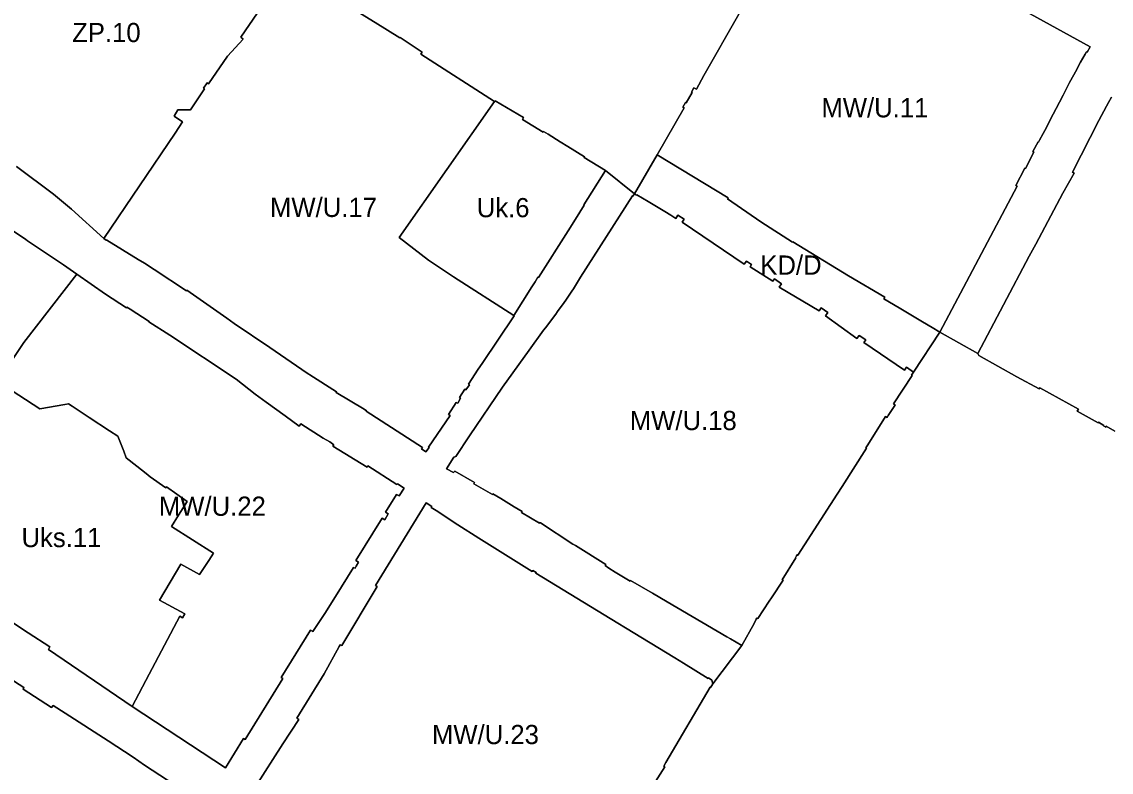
# Model space of a CAD drawing. Extents: x 7423367 to 7424726, y 5546744 to 5548391.
# Drawn here: x 7423643.2 to 7423927, y 5547840.8 to 5548036.2 of the extents above; entities that cross this region are included whole.
import ezdxf

# ---------------------------------------------------------------- set-up
doc = ezdxf.new("R2010")
doc.units = 0
doc.layers.add('linie_rozgraniczajace', color=7, linetype='Continuous')
doc.layers.add('oznaczenia_przeznaczen', color=7, linetype='Continuous')

msp = doc.modelspace()

# ---------------------------------------------------------------- linework, layer by layer
at = {"layer": 'linie_rozgraniczajace'}
for points in [[(7423885.09, 5548049.88), (7423921.52, 5548029.77), (7423920.73, 5548028.36), (7423920.59, 5548028.44), (7423920.26, 5548027.84), (7423919.06, 5548025.7), (7423917.72, 5548023.24), (7423916.54, 5548021.09), (7423916.19, 5548020.45), (7423914.8, 5548017.67), (7423914.53, 5548017.11), (7423913.56, 5548015.33), (7423911.05, 5548010.55), (7423910.14, 5548008.72), (7423909.29, 5548007.19), (7423908.36, 5548005.42), (7423908.1, 5548004.94), (7423908.01, 5548004.98), (7423906.64, 5548002.5), (7423906.89, 5548002.31), (7423904.69, 5547998.03), (7423904.56, 5547998.1), (7423902.22, 5547993.58), (7423902.52, 5547993.43), (7423882.35, 5547955.46), (7423880.38, 5547956.62), (7423877.9, 5547958.07), (7423872.18, 5547961.46), (7423870.28, 5547962.6), (7423867.78, 5547964.11), (7423868.05, 5547964.53), (7423858.62, 5547970.07), (7423844.04, 5547978.98), (7423843.97, 5547978.87), (7423835.77, 5547984.17), (7423827.04, 5547990.13), (7423827.22, 5547990.39), (7423808.74, 5548001.62), (7423815.79, 5548013.83), (7423815.44, 5548014.04), (7423816.14, 5548015.19), (7423816.27, 5548015.11), (7423817.81, 5548017.81), (7423817.67, 5548017.89), (7423818.27, 5548019.04), (7423818.96, 5548018.68), (7423820.91, 5548022.25), (7423830.03, 5548038.21)], [(7423927.11, 5548016.65), (7423926.3, 5548015.23), (7423925.83, 5548014.29), (7423923.84, 5548010.57), (7423916.91, 5547997.09), (7423917.36, 5547996.85), (7423914.45, 5547991.58), (7423907.39, 5547978.36), (7423905.67, 5547975.22), (7423892.25, 5547949.89), (7423882.35, 5547955.46), (7423902.52, 5547993.43), (7423902.22, 5547993.58), (7423904.56, 5547998.1), (7423904.69, 5547998.03), (7423906.89, 5548002.31), (7423906.64, 5548002.5), (7423908.01, 5548004.98), (7423908.1, 5548004.94), (7423908.36, 5548005.42), (7423909.29, 5548007.19), (7423910.14, 5548008.72), (7423911.05, 5548010.55), (7423913.56, 5548015.33), (7423914.53, 5548017.11), (7423914.8, 5548017.67), (7423916.19, 5548020.45), (7423916.54, 5548021.09), (7423917.72, 5548023.24), (7423919.06, 5548025.7), (7423920.26, 5548027.84), (7423920.59, 5548028.44), (7423920.73, 5548028.36), (7423921.52, 5548029.77), (7423885.09, 5548049.88)], [(7423710.1, 5548046.67), (7423700.22, 5548032.28), (7423700.88, 5548031.75), (7423696.81, 5548027.33), (7423691.85, 5548020.1), (7423691.5, 5548020.34), (7423690.54, 5548018.95), (7423690.83, 5548018.75), (7423687.17, 5548013.29), (7423683.85, 5548013.29), (7423682.85, 5548011.68), (7423685.07, 5548010.16), (7423683.14, 5548007.28), (7423664.55, 5547979.8), (7423656.16, 5547987.48), (7423651.46, 5547991.4), (7423641.85, 5547998.56)], [(7423725.35, 5548042.21), (7423735.28, 5548036.08), (7423741.7, 5548032.06), (7423741.77, 5548032.13), (7423747.51, 5548028.35), (7423747.14, 5548027.86), (7423766.34, 5548015.45), (7423741.48, 5547980.05), (7423749.19, 5547974.17), (7423755.66, 5547969.79), (7423771.37, 5547959.73), (7423771.51, 5547959.64), (7423763.12, 5547947.28), (7423762.11, 5547945.8), (7423759.6, 5547941.86), (7423759.84, 5547941.68), (7423758.89, 5547940.43), (7423758.64, 5547940.57), (7423757.19, 5547938.41), (7423757.52, 5547938.21), (7423756.79, 5547936.94), (7423756.34, 5547937.08), (7423754.37, 5547933.96), (7423754.78, 5547933.68), (7423749.15, 5547925.51), (7423749.3, 5547925.41), (7423748.49, 5547924.24), (7423747.31, 5547925.01), (7423747.55, 5547925.37), (7423732.92, 5547934.82), (7423733, 5547934.95), (7423732.36, 5547935.34), (7423725.08, 5547939.75), (7423725.15, 5547939.86), (7423718.24, 5547944.32), (7423717.98, 5547944.48), (7423717.52, 5547944.76), (7423707.84, 5547951.4), (7423698.55, 5547957.67), (7423696.59, 5547959.07), (7423686.22, 5547966.37), (7423686.11, 5547966.22), (7423677.64, 5547971.78), (7423675.13, 5547973.35), (7423673.55, 5547974.36), (7423665.31, 5547979.42), (7423665.19, 5547979.37), (7423664.55, 5547979.8), (7423683.14, 5548007.28), (7423685.07, 5548010.16), (7423682.85, 5548011.68), (7423683.85, 5548013.29), (7423687.17, 5548013.29), (7423690.83, 5548018.75), (7423690.54, 5548018.95), (7423691.5, 5548020.34), (7423691.85, 5548020.1), (7423696.81, 5548027.33), (7423700.88, 5548031.75), (7423700.22, 5548032.28), (7423710.1, 5548046.67)], [(7423830.03, 5548038.21), (7423820.91, 5548022.25), (7423818.96, 5548018.68), (7423818.27, 5548019.04), (7423817.67, 5548017.89), (7423817.81, 5548017.81), (7423816.27, 5548015.11), (7423816.14, 5548015.19), (7423815.44, 5548014.04), (7423815.79, 5548013.83), (7423808.74, 5548001.62), (7423802.79, 5547991.41), (7423795.28, 5547997.5), (7423789.69, 5548000.9), (7423789.79, 5548001.07), (7423785.47, 5548003.77), (7423783.44, 5548005.02), (7423780.3, 5548006.95), (7423779.1, 5548007.67), (7423779.01, 5548007.51), (7423773.64, 5548010.84), (7423773.87, 5548011.29), (7423766.49, 5548015.69), (7423766.34, 5548015.45), (7423747.14, 5548027.86), (7423747.51, 5548028.35), (7423741.77, 5548032.13), (7423741.7, 5548032.06), (7423735.28, 5548036.08), (7423725.35, 5548042.21)], [(7423927.97, 5547929.6), (7423925.73, 5547930.91), (7423925.61, 5547930.67), (7423924.99, 5547930.99), (7423925.07, 5547931.14), (7423923.71, 5547931.94), (7423923.61, 5547931.77), (7423918.19, 5547934.83), (7423918.54, 5547935.37), (7423908.44, 5547940.95), (7423908.29, 5547940.68), (7423902.4, 5547943.78), (7423892.52, 5547949.37), (7423892.25, 5547949.89), (7423905.67, 5547975.22), (7423907.39, 5547978.36), (7423914.45, 5547991.58), (7423917.36, 5547996.85), (7423916.91, 5547997.09), (7423923.84, 5548010.57), (7423925.83, 5548014.29), (7423926.3, 5548015.23), (7423927.11, 5548016.65)], [(7423641.85, 5547998.56), (7423651.46, 5547991.4), (7423656.16, 5547987.48), (7423664.55, 5547979.8), (7423665.19, 5547979.37), (7423665.31, 5547979.42), (7423673.55, 5547974.36), (7423675.13, 5547973.35), (7423677.64, 5547971.78), (7423686.11, 5547966.22), (7423686.22, 5547966.37), (7423696.59, 5547959.07), (7423698.55, 5547957.67), (7423707.84, 5547951.4), (7423717.52, 5547944.76), (7423717.98, 5547944.48), (7423718.24, 5547944.32), (7423725.15, 5547939.86), (7423725.08, 5547939.75), (7423732.36, 5547935.34), (7423733, 5547934.95), (7423732.92, 5547934.82), (7423747.55, 5547925.37), (7423747.31, 5547925.01), (7423748.49, 5547924.24), (7423749.3, 5547925.41), (7423749.15, 5547925.51), (7423754.78, 5547933.68), (7423754.37, 5547933.96), (7423756.34, 5547937.08), (7423756.79, 5547936.94), (7423757.52, 5547938.21), (7423757.19, 5547938.41), (7423758.64, 5547940.57), (7423758.89, 5547940.43), (7423759.84, 5547941.68), (7423759.6, 5547941.86), (7423762.11, 5547945.8), (7423763.12, 5547947.28), (7423771.51, 5547959.64), (7423771.37, 5547959.73), (7423776.07, 5547967.19), (7423776.93, 5547968.57), (7423777.67, 5547969.74), (7423777.81, 5547969.65), (7423785.56, 5547981.81), (7423787.49, 5547984.84), (7423789.75, 5547988.46), (7423789.6, 5547988.55), (7423795.28, 5547997.5), (7423802.79, 5547991.41), (7423802.43, 5547990.81), (7423802.3, 5547990.92), (7423788.74, 5547969.75), (7423788.8, 5547969.71), (7423786.9, 5547966.72), (7423786.47, 5547966.08), (7423784.94, 5547963.75), (7423784.5, 5547963.13), (7423782.78, 5547960.76), (7423782.3, 5547960.11), (7423779.61, 5547956.53), (7423779.16, 5547955.91), (7423775.37, 5547950.77), (7423768.42, 5547941.11), (7423759.88, 5547928.43), (7423756.26, 5547923.03), (7423755.74, 5547922.87), (7423753.88, 5547919.84), (7423755.63, 5547918.85), (7423756.05, 5547919.24), (7423761.16, 5547916.31), (7423760.94, 5547915.93), (7423765.79, 5547913.12), (7423765.92, 5547913.33), (7423767.98, 5547912.06), (7423771.49, 5547909.94), (7423773.52, 5547908.72), (7423773.38, 5547908.48), (7423778.05, 5547905.65), (7423778.18, 5547905.87), (7423778.3, 5547905.79), (7423786.8, 5547900.23), (7423787.47, 5547899.82), (7423795.34, 5547894.88), (7423795.18, 5547894.64), (7423796.14, 5547893.99), (7423797.81, 5547892.96), (7423801.71, 5547890.56), (7423801.81, 5547890.73), (7423807.55, 5547887.48), (7423811.38, 5547885.21), (7423826.89, 5547876.06), (7423827.82, 5547875.57), (7423830.78, 5547873.78), (7423823.24, 5547863.84), (7423822.97, 5547864.82), (7423822.08, 5547865.39), (7423822.01, 5547865.27), (7423815.61, 5547869.21), (7423813.35, 5547870.61), (7423800.51, 5547878.46), (7423798.51, 5547879.65), (7423777.08, 5547892.63), (7423777.19, 5547892.82), (7423776.34, 5547893.37), (7423776.18, 5547893.06), (7423762.27, 5547901.73), (7423756.79, 5547905.21), (7423751.12, 5547908.95), (7423749.88, 5547909.77), (7423750.04, 5547910.02), (7423748.55, 5547910.97), (7423735.38, 5547889.46), (7423735.79, 5547889.21), (7423726.57, 5547873.83), (7423726.18, 5547874.03), (7423725.9, 5547873.53), (7423722, 5547866.46), (7423714.83, 5547854.87), (7423715.35, 5547854.54), (7423711.24, 5547848.23), (7423703.96, 5547836.97)], [(7423630.41, 5547988.72), (7423644.27, 5547979.52), (7423644.67, 5547979.21), (7423654.03, 5547972.95), (7423657.55, 5547970.55), (7423643.76, 5547952.76), (7423636.86, 5547942.57)], [(7423640.25, 5547880.13), (7423644.87, 5547877.13), (7423650.51, 5547873.45), (7423650.14, 5547872.82), (7423671.93, 5547857.91), (7423696.24, 5547841.95), (7423700.96, 5547849.62), (7423701.41, 5547849.32), (7423711.16, 5547865.26), (7423710.73, 5547865.53), (7423718.45, 5547877.85), (7423719, 5547877.48), (7423722.13, 5547882.17), (7423724.89, 5547886.57), (7423729.64, 5547894.17), (7423730.03, 5547893.96), (7423730.35, 5547894.51), (7423730.94, 5547895.51), (7423730.22, 5547895.96), (7423737.11, 5547907.02), (7423737.79, 5547906.58), (7423738.69, 5547908.13), (7423737.97, 5547908.55), (7423740.86, 5547913.16), (7423741.48, 5547912.77), (7423742.78, 5547914.81), (7423741.04, 5547915.94), (7423740.94, 5547915.78), (7423733.36, 5547920.65), (7423733.14, 5547920.26), (7423724.27, 5547925.69), (7423724.5, 5547926.1), (7423724.11, 5547926.36), (7423723.42, 5547926.83), (7423721.68, 5547927.85), (7423715.93, 5547931.57), (7423715.49, 5547930.91), (7423711.79, 5547933.62), (7423706.86, 5547937.2), (7423703.96, 5547939.29), (7423699.06, 5547943.2), (7423681.8, 5547954.6), (7423676.33, 5547958.09), (7423676.41, 5547958.22), (7423671.42, 5547961.38), (7423670.57, 5547961.92), (7423670.51, 5547961.8), (7423664.98, 5547965.28), (7423657.55, 5547970.55), (7423654.03, 5547972.95), (7423644.67, 5547979.21), (7423644.27, 5547979.52), (7423630.41, 5547988.72)], [(7423807.72, 5547837.46), (7423810.74, 5547842.25), (7423810.48, 5547842.41), (7423811.01, 5547843.31), (7423822.57, 5547863), (7423822.68, 5547862.93), (7423823.24, 5547863.84), (7423830.78, 5547873.78), (7423833.97, 5547879.57), (7423834.55, 5547880.7), (7423834.7, 5547880.95), (7423834.92, 5547880.82), (7423837.93, 5547885.35), (7423838.53, 5547886.25), (7423841.52, 5547890.8), (7423841.31, 5547890.94), (7423844.82, 5547896.62), (7423844.74, 5547896.68), (7423845.06, 5547897.15), (7423845.24, 5547897.41), (7423845.34, 5547897.34), (7423855.63, 5547913.2), (7423856.9, 5547915.19), (7423863.26, 5547925.17), (7423863.06, 5547925.31), (7423863.62, 5547926.11), (7423868.2, 5547933.46), (7423868.63, 5547933.19), (7423868.96, 5547933.68), (7423870.49, 5547936.03), (7423870.77, 5547936.49), (7423870.33, 5547936.75), (7423875.16, 5547944.17), (7423875.04, 5547944.25), (7423875.5, 5547945.01), (7423882.35, 5547955.46), (7423892.25, 5547949.89), (7423892.52, 5547949.37), (7423902.4, 5547943.78), (7423908.29, 5547940.68), (7423908.44, 5547940.95), (7423918.54, 5547935.37), (7423918.19, 5547934.83), (7423923.61, 5547931.77), (7423923.71, 5547931.94), (7423925.07, 5547931.14), (7423924.99, 5547930.99), (7423925.61, 5547930.67), (7423925.73, 5547930.91), (7423927.97, 5547929.6)], [(7423636.86, 5547942.57), (7423647.87, 5547935.43), (7423654.41, 5547936.55), (7423655.4, 5547936.74), (7423656.34, 5547936.12), (7423660.74, 5547933.23), (7423666.01, 5547929.73), (7423668.23, 5547928.36), (7423669.81, 5547924.41), (7423670.38, 5547922.73), (7423673.14, 5547920.55), (7423675.58, 5547918.59), (7423676.62, 5547917.76), (7423680.74, 5547914.89), (7423680.88, 5547915.1), (7423686.29, 5547911.35), (7423684.03, 5547907.72), (7423682.18, 5547904.78), (7423693.17, 5547897.85), (7423691.9, 5547895.95), (7423689.46, 5547892.29), (7423684.65, 5547894.97), (7423679.03, 5547885.65), (7423685.63, 5547882.07), (7423685.03, 5547881.04), (7423684.35, 5547881.43), (7423676.36, 5547866.35), (7423671.93, 5547857.91), (7423650.14, 5547872.82), (7423650.51, 5547873.45), (7423644.87, 5547877.13), (7423640.25, 5547880.13)], [(7423703.96, 5547836.97), (7423711.24, 5547848.23), (7423715.35, 5547854.54), (7423714.83, 5547854.87), (7423722, 5547866.46), (7423725.9, 5547873.53), (7423726.18, 5547874.03), (7423726.57, 5547873.83), (7423735.79, 5547889.21), (7423735.38, 5547889.46), (7423748.55, 5547910.97), (7423750.04, 5547910.02), (7423749.88, 5547909.77), (7423751.12, 5547908.95), (7423756.79, 5547905.21), (7423762.27, 5547901.73), (7423776.18, 5547893.06), (7423776.34, 5547893.37), (7423777.19, 5547892.82), (7423777.08, 5547892.63), (7423798.51, 5547879.65), (7423800.51, 5547878.46), (7423813.35, 5547870.61), (7423815.61, 5547869.21), (7423822.01, 5547865.27), (7423822.08, 5547865.39), (7423822.97, 5547864.82), (7423823.24, 5547863.84), (7423822.68, 5547862.93), (7423822.57, 5547863), (7423811.01, 5547843.31), (7423810.48, 5547842.41), (7423810.74, 5547842.25), (7423807.72, 5547837.46)], [(7423599.17, 5547838.24), (7423590.07, 5547843.46), (7423595.31, 5547852.66), (7423594.21, 5547853.26), (7423605.47, 5547872.61), (7423606.55, 5547871.98), (7423611.45, 5547880.43), (7423620.5, 5547875.26), (7423621.63, 5547877.07), (7423643.75, 5547862.87), (7423643.56, 5547862.47), (7423650.96, 5547857.64), (7423651.33, 5547858.21), (7423654.49, 5547856.17), (7423665.68, 5547848.96), (7423672.17, 5547844.7), (7423675.14, 5547842.66), (7423691.1, 5547832.28)], [(7423691.1, 5547832.28), (7423675.14, 5547842.66), (7423672.17, 5547844.7), (7423665.68, 5547848.96), (7423654.49, 5547856.17), (7423651.33, 5547858.21), (7423650.96, 5547857.64), (7423643.56, 5547862.47), (7423643.75, 5547862.87), (7423621.63, 5547877.07)]]:
    msp.add_lwpolyline(points, dxfattribs=at)
for points in [[(7423741.48, 5547980.05), (7423766.34, 5548015.45), (7423766.49, 5548015.69), (7423773.87, 5548011.29), (7423773.64, 5548010.84), (7423779.01, 5548007.51), (7423779.1, 5548007.67), (7423780.3, 5548006.95), (7423783.44, 5548005.02), (7423785.47, 5548003.77), (7423789.79, 5548001.07), (7423789.69, 5548000.9), (7423795.28, 5547997.5), (7423789.6, 5547988.55), (7423789.75, 5547988.46), (7423787.49, 5547984.84), (7423785.56, 5547981.81), (7423777.81, 5547969.65), (7423777.67, 5547969.74), (7423776.93, 5547968.57), (7423776.07, 5547967.19), (7423771.37, 5547959.73), (7423755.66, 5547969.79), (7423749.19, 5547974.17)], [(7423802.79, 5547991.41), (7423808.74, 5548001.62), (7423827.22, 5547990.39), (7423827.04, 5547990.13), (7423835.77, 5547984.17), (7423843.97, 5547978.87), (7423844.04, 5547978.98), (7423858.62, 5547970.07), (7423868.05, 5547964.53), (7423867.78, 5547964.11), (7423870.28, 5547962.6), (7423872.18, 5547961.46), (7423877.9, 5547958.07), (7423880.38, 5547956.62), (7423882.35, 5547955.46), (7423875.5, 5547945.01), (7423873.66, 5547946.27), (7423873.13, 5547945.49), (7423862.59, 5547952.71), (7423863.06, 5547953.39), (7423861.35, 5547954.55), (7423860.77, 5547953.78), (7423852.59, 5547959.66), (7423853.2, 5547960.51), (7423851.5, 5547961.73), (7423850.93, 5547960.94), (7423840.56, 5547967.12), (7423841.16, 5547968.02), (7423839.27, 5547969.29), (7423838.87, 5547968.71), (7423832.94, 5547972.46), (7423833.31, 5547973), (7423831.97, 5547973.92), (7423831.44, 5547973.14), (7423815.27, 5547984.07), (7423815.78, 5547984.83), (7423814.16, 5547985.93), (7423813.62, 5547985.06), (7423812.32, 5547985.87), (7423810.71, 5547986.84), (7423806.36, 5547989.42), (7423803.43, 5547991.21), (7423803.35, 5547991.09)], [(7423753.88, 5547919.84), (7423755.74, 5547922.87), (7423756.26, 5547923.03), (7423759.88, 5547928.43), (7423768.42, 5547941.11), (7423775.37, 5547950.77), (7423779.16, 5547955.91), (7423779.61, 5547956.53), (7423782.3, 5547960.11), (7423782.78, 5547960.76), (7423784.5, 5547963.13), (7423784.94, 5547963.75), (7423786.47, 5547966.08), (7423786.9, 5547966.72), (7423788.8, 5547969.71), (7423788.74, 5547969.75), (7423802.3, 5547990.92), (7423802.43, 5547990.81), (7423802.79, 5547991.41), (7423803.35, 5547991.09), (7423803.43, 5547991.21), (7423806.36, 5547989.42), (7423810.71, 5547986.84), (7423812.32, 5547985.87), (7423813.62, 5547985.06), (7423814.16, 5547985.93), (7423815.78, 5547984.83), (7423815.27, 5547984.07), (7423831.44, 5547973.14), (7423831.97, 5547973.92), (7423833.31, 5547973), (7423832.94, 5547972.46), (7423838.87, 5547968.71), (7423839.27, 5547969.29), (7423841.16, 5547968.02), (7423840.56, 5547967.12), (7423850.93, 5547960.94), (7423851.5, 5547961.73), (7423853.2, 5547960.51), (7423852.59, 5547959.66), (7423860.77, 5547953.78), (7423861.35, 5547954.55), (7423863.06, 5547953.39), (7423862.59, 5547952.71), (7423873.13, 5547945.49), (7423873.66, 5547946.27), (7423875.5, 5547945.01), (7423875.04, 5547944.25), (7423875.16, 5547944.17), (7423870.33, 5547936.75), (7423870.77, 5547936.49), (7423870.49, 5547936.03), (7423868.96, 5547933.68), (7423868.63, 5547933.19), (7423868.2, 5547933.46), (7423863.62, 5547926.11), (7423863.06, 5547925.31), (7423863.26, 5547925.17), (7423856.9, 5547915.19), (7423855.63, 5547913.2), (7423845.34, 5547897.34), (7423845.24, 5547897.41), (7423845.06, 5547897.15), (7423844.74, 5547896.68), (7423844.82, 5547896.62), (7423841.31, 5547890.94), (7423841.52, 5547890.8), (7423838.53, 5547886.25), (7423837.93, 5547885.35), (7423834.92, 5547880.82), (7423834.7, 5547880.95), (7423834.55, 5547880.7), (7423833.97, 5547879.57), (7423830.78, 5547873.78), (7423827.82, 5547875.57), (7423826.89, 5547876.06), (7423811.38, 5547885.21), (7423807.55, 5547887.48), (7423801.81, 5547890.73), (7423801.71, 5547890.56), (7423797.81, 5547892.96), (7423796.14, 5547893.99), (7423795.18, 5547894.64), (7423795.34, 5547894.88), (7423787.47, 5547899.82), (7423786.8, 5547900.23), (7423778.3, 5547905.79), (7423778.18, 5547905.87), (7423778.05, 5547905.65), (7423773.38, 5547908.48), (7423773.52, 5547908.72), (7423771.49, 5547909.94), (7423767.98, 5547912.06), (7423765.92, 5547913.33), (7423765.79, 5547913.12), (7423760.94, 5547915.93), (7423761.16, 5547916.31), (7423756.05, 5547919.24), (7423755.63, 5547918.85)], [(7423636.86, 5547942.57), (7423643.76, 5547952.76), (7423657.55, 5547970.55), (7423664.98, 5547965.28), (7423670.51, 5547961.8), (7423670.57, 5547961.92), (7423671.42, 5547961.38), (7423676.41, 5547958.22), (7423676.33, 5547958.09), (7423681.8, 5547954.6), (7423699.06, 5547943.2), (7423703.96, 5547939.29), (7423706.86, 5547937.2), (7423711.79, 5547933.62), (7423715.49, 5547930.91), (7423715.93, 5547931.57), (7423721.68, 5547927.85), (7423723.42, 5547926.83), (7423724.11, 5547926.36), (7423724.5, 5547926.1), (7423724.27, 5547925.69), (7423733.14, 5547920.26), (7423733.36, 5547920.65), (7423740.94, 5547915.78), (7423741.04, 5547915.94), (7423742.78, 5547914.81), (7423741.48, 5547912.77), (7423740.86, 5547913.16), (7423737.97, 5547908.55), (7423738.69, 5547908.13), (7423737.79, 5547906.58), (7423737.11, 5547907.02), (7423730.22, 5547895.96), (7423730.94, 5547895.51), (7423730.35, 5547894.51), (7423730.03, 5547893.96), (7423729.64, 5547894.17), (7423724.89, 5547886.57), (7423722.13, 5547882.17), (7423719, 5547877.48), (7423718.45, 5547877.85), (7423710.73, 5547865.53), (7423711.16, 5547865.26), (7423701.41, 5547849.32), (7423700.96, 5547849.62), (7423696.24, 5547841.95), (7423671.93, 5547857.91), (7423676.36, 5547866.35), (7423684.35, 5547881.43), (7423685.03, 5547881.04), (7423685.63, 5547882.07), (7423679.03, 5547885.65), (7423684.65, 5547894.97), (7423689.46, 5547892.29), (7423691.9, 5547895.95), (7423693.17, 5547897.85), (7423682.18, 5547904.78), (7423684.03, 5547907.72), (7423686.29, 5547911.35), (7423680.88, 5547915.1), (7423680.74, 5547914.89), (7423676.62, 5547917.76), (7423675.58, 5547918.59), (7423673.14, 5547920.55), (7423670.38, 5547922.73), (7423669.81, 5547924.41), (7423668.23, 5547928.36), (7423666.01, 5547929.73), (7423660.74, 5547933.23), (7423656.34, 5547936.12), (7423655.4, 5547936.74), (7423654.41, 5547936.55), (7423647.87, 5547935.43)]]:
    msp.add_lwpolyline(points, close=True, dxfattribs=at)

# ---------------------------------------------------------------- texts
at = {"layer": 'oznaczenia_przeznaczen'}
for s, p in [('ZP.10', (7423656.31, 5548030.96)), ('MW/U.11', (7423851.53, 5548011.36)), ('MW/U.17', (7423707.86, 5547985.42)), ('Uk.6', (7423761.73, 5547985.35)), ('KD/D', (7423835.6, 5547970.39)), ('MW/U.18', (7423801.6, 5547929.92)), ('MW/U.22', (7423678.91, 5547907.6)), ('Uks.11', (7423643.12, 5547899.44)), ('MW/U.23', (7423750.06, 5547848.14))]:
    msp.add_text(s, height=5, dxfattribs=at).set_placement(p)

doc.saveas('drawing.dxf')
